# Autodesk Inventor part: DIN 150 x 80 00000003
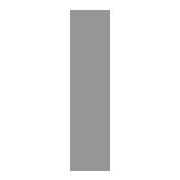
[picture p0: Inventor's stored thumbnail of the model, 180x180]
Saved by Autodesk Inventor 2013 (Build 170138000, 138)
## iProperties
_CCFamilyMember: 150
_CCFamilyDisplayName: DIN EN 10058 - Hot rolled flat steel bars for general purposes
_FrameMemberDoc: Frame Member File
_Version: 15.0.0
Created: 2009-11
Part Number: DIN 150 x 80 00000003
Material: Steel, Mild
Description: Hot rolled flat steel bars for general purposes
Document SubType Name: Modeling
Standard: DIN
Designer: pokornp
Standard Revision: 2004
Standards Organization: DIN
Language: en-US
Size Designation: 150 x 80
Categories: <MemberInstance><Categories><Category DisplayName="Structural Shapes" InternalName="089c4875-fa83-4c05-b084-43b9cc11f5ed" Mnemonic="GRDR"><CategoryParameter Dis
Stock Number: 150 x 80
Density: 7.86 g/cm^3
IsCustomPart: 1
G_L: 900.000 mm
G_W: 80.000 mm
G_H: 150.000 mm
Author: pokornp
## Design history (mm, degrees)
node "Start plane"
node "End plane"
sketch "Sketch"
  geometry: L1 (40, -75)-(-40, -75); L2 (-40, -75)-(-40, 75); L3 (-40, 75)-(40, 75); L4 (40, 75)-(40, -75); L5 (-6, 0)-(8, 0); L6 (0, -30)-(0, 40); L7 (0, 105)-(0, -105) reference; L8 (-56, 0)-(56, 0) reference
  constraints: 12 end point, 2 collinear, 2 parallel, 1 horizontal, 1 perpendicular
  dimensions: "d0" = 150 distance between parallel lines of L3 L1 (= G_W); "d1" = 80 distance between parallel lines of L4 L2 (= G_H); "d4" = 40 distance between parallel lines of L6 L4 (= 0.5 x d1); "d5" = 75 distance between parallel lines of L5 L3 (= 0.5 x d0)
extrude "Body" new body sketch "Sketch" stored distance "d2" = 900 (= G_L); taper "d3" = 0 deg
node "Driven Length"
  sketch "Sketch3"
    geometry: L1 (0, 0)-(10, 0) reference
    constraints: 2 end point, 1 horizontal
  workplane "Work Plane3"
  sketch "Sketch4"
    geometry: L1 (-2, 0)-(12, 0) reference; L2 (-2, 900)-(12, 900) reference
    dimensions: "d9" = 900 distance between parallel lines of L1 L2 (derived)
body "Solid1"
other parameters: "G_W" = 150 [user parameter; used in 1 equation term], "G_H" = 80 [user parameter; used in 1 equation term], "G_L" = 900 (= d9) [user parameter; used in 1 equation term], "G_OFFSET_START" = 0 [user parameter; used in 1 equation term], "G_OFFSET_END" = 0 [user parameter; used in 1 equation term], "d6" = 0 (computed from G_OFFSET_START), "d8" = 90 deg, "MAS" = 9.42 [user parameter]
